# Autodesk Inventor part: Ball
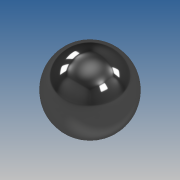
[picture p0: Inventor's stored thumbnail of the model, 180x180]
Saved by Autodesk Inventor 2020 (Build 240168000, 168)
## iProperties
Created: 2019-10
Part Number: Ball
Material: Generic
Document SubType Name: Modeling
Designer: yello
Density: 1 g/cm^3
Appearance: Default
Author: yello
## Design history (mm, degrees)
sketch "Sketch1"
  geometry: L1 (1.5, 0)-(-1.5, 0); A1 r 1.5 centre (0, 0) between (1.5, 0) and (-1.5, 0); 1 further point
  constraints: 2 end point, 2 point on circle, 1 centre point, 1 coincident, 1 horizontal
  dimensions: "d0" = 3 diameter of A1
revolve "Revolution1" sketch "Sketch1" stored, may be unused: angle "d1" = 90 deg
body "Solid1"
